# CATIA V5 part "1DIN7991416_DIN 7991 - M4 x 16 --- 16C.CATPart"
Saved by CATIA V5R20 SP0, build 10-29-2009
Part number: 1DIN7991416_DIN 7991 - M4 x 16 --- 16C
Revision: ANY
Definition: UNKNOWN
Nomenclature: 1DIN7991416_DIN 7991 - M4 x 16 --- 16C
Source: Unknown
Bounding box of the stored display mesh (mm): x 0 to 16, y -3.633 to 3.633, z -3.82 to 3.82
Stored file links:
  C:\Users\Utente\Desktop\IO LAVORO\3D X SITO CF\CUMSA\3D files PW\pw060822\pw060822_ejection\1DIN7991416_DIN 7991 - M4 x 16 --- 16C.CATPart
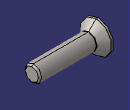
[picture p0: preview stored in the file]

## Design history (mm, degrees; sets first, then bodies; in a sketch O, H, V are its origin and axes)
Body1 "Hex" (main body)
  Solid1: solid without history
